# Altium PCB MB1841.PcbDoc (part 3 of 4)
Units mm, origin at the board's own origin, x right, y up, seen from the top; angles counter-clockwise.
Board outline 70 x 82.5 mm, 4 copper layers (Top Layer, Signal Layer 1, Signal Layer 2, Bottom Layer), stack 1.49 mm thick; 252 components, 169 nets, 1058 pads, 796 vias.
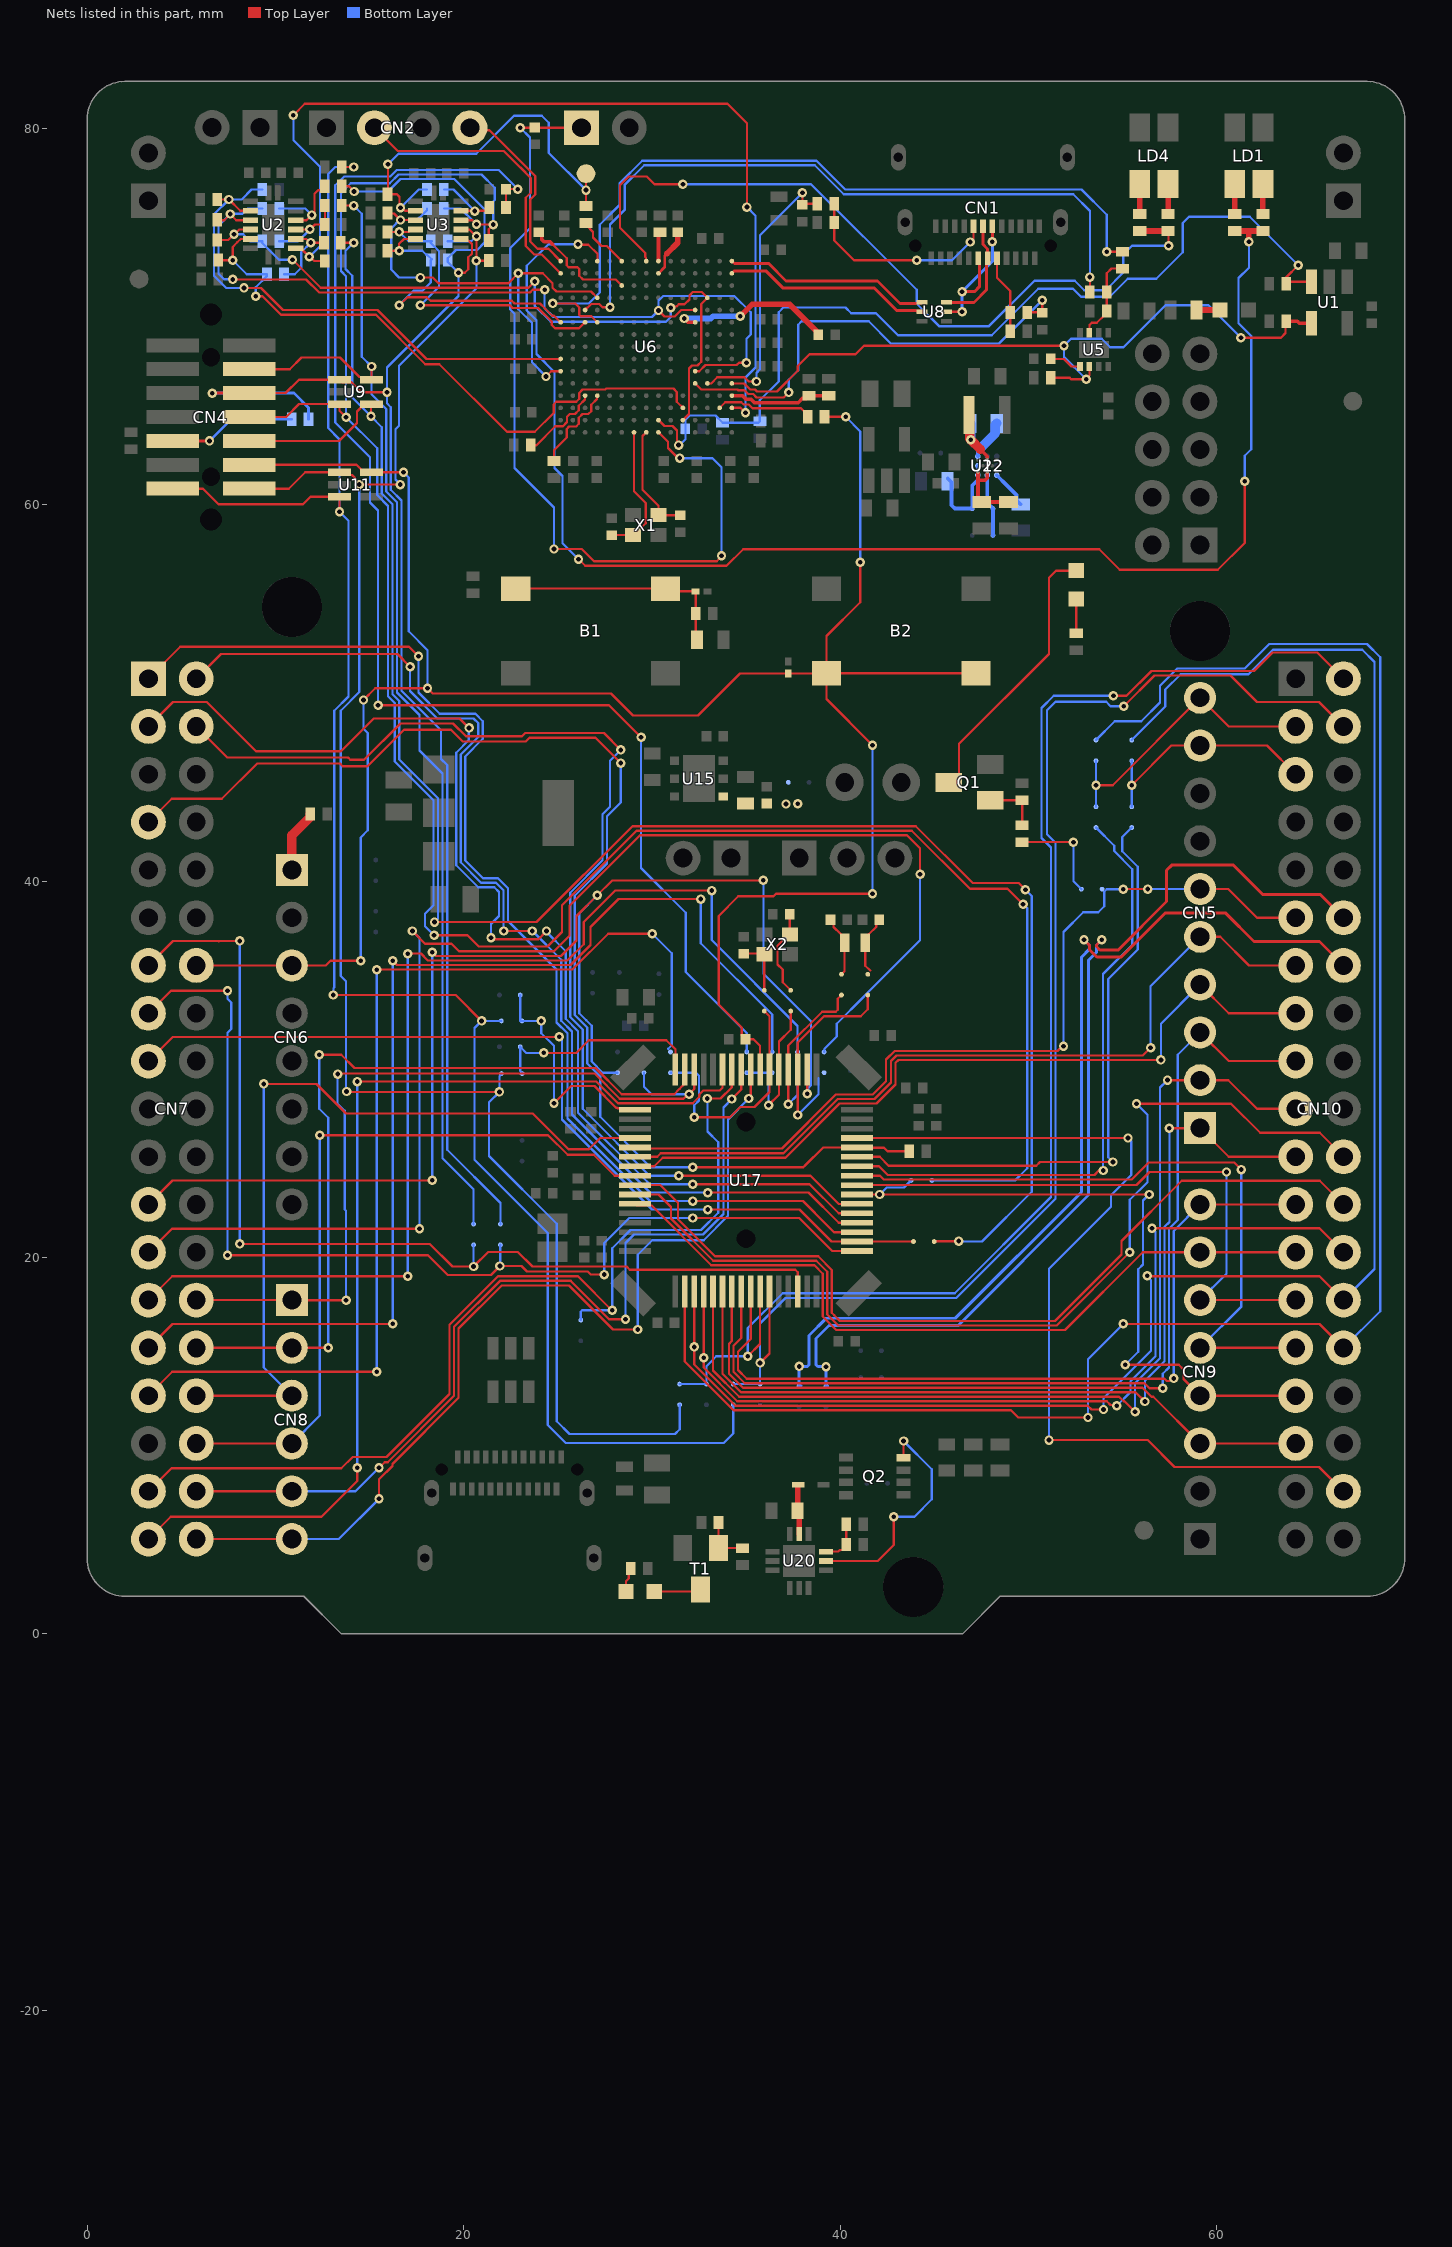
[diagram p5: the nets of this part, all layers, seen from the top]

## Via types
v1: diameter 0.5, hole 0.25, Top Layer to Bottom Layer, tented both sides, 796 vias

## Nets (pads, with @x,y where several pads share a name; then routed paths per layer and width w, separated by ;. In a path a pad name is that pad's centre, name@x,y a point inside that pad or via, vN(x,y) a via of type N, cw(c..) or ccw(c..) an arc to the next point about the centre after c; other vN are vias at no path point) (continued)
JTDI_BP: R21.1 R109.2 U2.11 | length 4.2
  Top Layer w0.12: U2.11@11.075,74.125 11.632,74.125 11.822,73.935 v1(11.88,73.935) ; v1@11.885,73.935 v1(11.88,73.935) ; v1@11.9,73.9 11.925,73.925 R21.1@12.575,73.925 ; v1@11.9,73.925 11.89,73.925 v1(11.88,73.935)
  Bottom Layer w0.12: R109.2@10.45,72.25 11.025,72.25 11.37,72.595 11.37,73.425 11.86,73.915 v1@11.865,73.915
MCO_BP: R7.1 R102.2 U3.14 | length 3.7
  Top Layer w0.12: U3.14@19.85,75.625 v1@20.61,75.625 ; v1(20.593,75.608) v1@20.61,75.625 ; R7.1@21.35,75.8 21.175,75.625 v1@20.61,75.625
  Bottom Layer w0.12: R102.2@18.95,76.75 19.452,76.75 20.487,75.715 v1@20.595,75.715
MCU.JTDI: CN4.10 R21.2 SB41.1 U9.4 | length 104.7
  Top Layer w0.12: CN4.10@8.602,63.395 13.37,63.395 14.325,64.35 14.325,64.955 14.72,65.35 U9.4@15.1,65.35 15.075,65.325 v1(15.075,64.7) ; R21.2@13.575,73.95 13.6,73.925 v1(14.15,73.925) ; v1(18.45,37.825) 23.875,37.825 28.975,42.925 44.025,42.925 47.05,39.9 49.5,39.9 v1(49.85,39.55) ; SB41.1@45,20.85 45.01,20.86 46.285,20.86 v1(46.3,20.875)
  Bottom Layer w0.12: v1(14.15,73.925) 13.72,73.495 13.72,72.53 14.075,72.175 14.075,65.7 v1(15.075,64.7) 15.65,64.125 15.65,60.604 16.22,60.034 16.22,49.926 16.575,49.571 16.575,46.464 18.64,44.399 18.64,38.008 18.45,37.818 v1(18.45,37.825) ; v1(46.3,20.875) 46.325,20.85 47.545,20.85 50.185,23.49 50.185,39.215 v1(49.85,39.55)
MCU.MCO: C6.1 R7.2 SB20.1 | length 74.4
  Top Layer w0.12: v1(15.45,49.35) 27.725,49.35 v1(29.425,47.65) ; R7.2@22.25,75.8 C6.1@22.25,76.775 v1(22.875,76.775)
  Bottom Layer w0.12: v1(15.45,49.35) 15.45,59.7 15.025,60.125 15.025,62.525 13.175,64.375 13.175,76.975 13.65,77.45 16.1,77.45 16.44,77.79 21.86,77.79 v1(22.875,76.775) ; v1(29.425,47.65) 29.425,40.7 31.8,38.325 31.8,35.175 32.5,34.475 35.04,31.935 SB20.1@35.04,30.925
MCU.SWCLK: CN4.6 R2.2 R66.1 R105.2 SB29.1 U3.11 U9.1 | length 87
  Top Layer w0.12: CN4.6@8.602,65.935 10.535,65.935 11.25,66.65 U9.1@13.4,66.65 13.54,66.51 14.04,66.51 14.576,65.974 15.924,65.974 v1(15.925,65.975) ; R2.2@13.525,76.925 13.9,76.925 v1(14.175,76.65) ; v1(19.725,72.325) 20.06,72.325 20.245,72.51 20.245,73.153 20.435,73.343 20.435,73.855 20.255,74.035 19.94,74.035 U3.11@19.85,74.125
  Top Layer w0.15: v1@6.641,65.93 v1(6.646,65.935) CN4.6@8.602,65.935
  Bottom Layer w0.12: v1(14.175,76.65) 15.979,76.65 16.639,77.31 19.5,77.31 21.112,75.698 21.112,74.617 ; 21.11,74.615 21.112,74.617 ; SB29.1@21.95,21.775 21.95,22.9 19.12,25.73 19.12,46.172 18.8,46.492 18.8,48.025 16.7,50.125 16.7,60.233 16.13,60.803 16.13,65.184 15.925,65.389 v1(15.925,65.975) 15.925,67.3 19.725,71.1 v1(19.725,72.325) 19.725,72.33 19.15,72.905 R105.2@19.15,73 19.15,73.095 19.595,73.54 20.72,73.54 21.112,73.932 21.112,74.617
  Bottom Layer w0.15: v1(6.646,65.935) 10.976,65.935 11.753,65.158 R66.1@11.753,64.541
MCU.SWDIO: CN4.4 R6.2 SB30.1 U9.5 | length 65.2
  Top Layer w0.12: CN4.4@8.7,67.205 10.755,67.205 11.375,67.825 13.425,67.825 14.46,66.79 14.96,66.79 U9.5@15.1,66.65 15.105,66.655 v1(15.105,67.35) ; R6.2@13.525,75.9 v1(14.15,75.9)
  Bottom Layer w0.12: v1(14.15,75.9) 14.589,75.461 14.589,67.866 v1(15.105,67.35) 15.105,65.87 15.89,65.085 15.89,60.703 16.46,60.133 16.46,50.026 17.65,48.836 17.65,47.45 17.65,46.95 18.88,45.72 18.88,25.27 20.525,23.625 SB30.1@20.525,21.775
MCU.SWO: CN4.8 R20.1 R103.2 SB28.2 U3.13 U9.3 | length 119.5
  Top Layer w0.12: CN4.8@8.602,64.665 10.565,64.665 11.25,65.35 U9.3@13.4,65.35 13.4,65 v1(13.75,64.65) ; v1(18.425,37.125) 20.2,37.125 20.8,36.525 24.45,36.525 25.225,37.3 25.225,38.725 29.185,42.685 43.815,42.685 46.9,39.6 48.9,39.6 v1(49.725,38.775) ; U3.13@19.85,75.125 20.457,75.125 v1(20.682,74.9) ; v1@20.7,74.9 20.705,74.895 21.565,74.895 v1(21.57,74.89) ; R20.1@21.32,74.055 R20.1@21.325,74.05 21.325,74.645 v1(21.57,74.89) ; v1@21.585,74.89 v1(21.57,74.89)
  Bottom Layer w0.12: v1(18.425,37.125) 17.95,37.6 17.95,38.275 18.4,38.725 18.4,44.3 16.335,46.365 16.335,49.472 15.98,49.827 15.98,59.934 15.4,60.514 15.4,63 v1(13.75,64.65) 13.75,72.15 13.48,72.42 13.48,76.563 13.997,77.08 16.069,77.08 16.539,77.55 20.945,77.55 21.65,76.845 21.65,76.19 21.57,76.11 21.57,74.925 v1@21.56,74.915 ; R103.2@18.95,75.75 19.832,75.75 20.595,74.987 v1@20.595,74.905 ; v1(21.57,74.89) v1@21.577,74.897 ; SB28.2@44.875,24.1 49.3,24.1 49.945,24.745 49.945,38.555 v1(49.725,38.775)
MCU.VCP_RX: CN4.13 R1.2 SB16.1 SB35.1 U11.3 | length 101.1
  Top Layer w0.12: CN4.13@4.55,60.85 6.15,60.85 6.975,60.025 11.461,60.025 11.861,60.425 U11.3@13.4,60.425 v1(13.4,59.625) ; v1(13.075,33.95) 19.575,33.95 v1(20.95,32.575) ; R1.2@13.525,77.95 v1(14.15,77.95)
  Bottom Layer w0.12: v1(13.075,33.95) 13.084,33.959 13.084,34.309 13.125,34.35 13.125,49.062 13.875,49.812 13.875,59.15 v1(13.4,59.625) ; v1@13.375,59.725 13.4,59.75 13.4,63.475 12.8,64.075 12.8,77.575 13.175,77.95 v1(14.15,77.95) ; v1(20.95,32.575) 20.575,32.2 20.575,25.2 24.47,21.305 24.47,11.101 25.426,10.145 33.82,10.145 34.325,10.65 SB35.1@34.325,12.175 ; 21.208,32.575 SB16.1@22,32.575
MCU.VCP_TX: CN4.14 R25.1 R104.2 SB26.1 SB37.1 U3.12 U11.1 | length 96.2
  Top Layer w0.12: CN4.14@8.602,60.855 10.705,60.855 11.575,61.725 U11.1@13.4,61.725 13.6,61.725 13.74,61.585 14.065,61.585 14.221,61.429 14.221,61.304 v1(14.45,61.075) v1(16.625,61.075) ; v1@14.003,28.8 v1(21.9,28.8) ; U3.12@19.85,74.625 19.86,74.615 20.305,74.615 20.61,74.31 v1@20.67,74.31 ; v1@20.665,74.32 20.678,74.307 20.678,72.978 v1(20.675,72.975) R25.1@21.325,72.975
  Bottom Layer w0.12: v1(13.775,28.825) 13.75,28.85 13.75,34.675 13.465,34.96 13.465,49.062 14.45,50.047 v1(14.45,61.075) ; v1(16.625,61.075) 16.625,61.088 16.37,61.343 16.37,64.009 16.561,64.2 16.561,67.386 20.675,71.5 v1(20.675,72.975) ; R104.2@19.15,74 20.407,74 v1(20.682,74.275) v1@20.68,74.28 ; SB26.1@22,29.775 22,29.739 21.9,29.639 v1(21.9,28.8) 21.35,28.25 21.35,25.4 24.95,21.8 24.95,11.3 25.625,10.625 31.225,10.625 31.475,10.875 SB37.1@31.475,12.175
NetB1_3: B1.3 B1.4 R48.2 R50.1 U13.1 | length 12.2
  Top Layer w0.12: B1.3@22.77,55.55 B1.4@30.72,55.55 30.87,55.4 U13.1@32.325,55.4 R48.2@32.325,54.225 32.325,52.9 R50.1@32.4,52.825
NetC8_2: C8.2 U6.F13 | length 6.1
  Top Layer w0.12: 24.725,73.85 25.475,73.1 25.475,72.725 25.575,72.625 26.05,72.625 26.145,72.53 26.145,72.174 26.344,71.975 28.075,71.975 U6.F13@28.4,71.65
  Top Layer w0.2: C8.2@24,74.475 24.15,74.325 24.15,74.1 24.275,73.975 24.6,73.975 24.725,73.85
NetC12_2: C12.2 U6.J14 | length 2.6
  Top Layer w0.15: U6.J14@30.35,72.3 30.68,72.63 30.68,73.23 30.8,73.35
  Top Layer w0.3: 30.8,73.35 31.375,73.925 C12.2@31.375,74.475 C12.2@31.375,74.494
NetC21_2: C21.2 U6.M10 | length 8.6
  Top Layer w0.2: v1(31.725,69.9) 31.925,69.7 U6.M10@32.295,69.7
  Top Layer w0.3: v1(34.7,70.025) 35.325,70.65 37.325,70.65 C21.2@38.75,69.225
  Bottom Layer w0.3: v1(31.725,69.9) 33.131,69.9 33.256,70.025 v1(34.7,70.025)
NetC24_2: C24.2 U5.1 | length 1.8
  Top Layer w0.12: C24.2@51.2,67.75 51.9,67.75 52.3,67.35 U5.1@52.75,67.35 U5.1@52.75,67.25
NetC44_2: C44.2 C46.2 SB8.1 U15.4
  other v1: 37.125,44.1 37.755,44.11
NetC71_2: C71.2 D1.2 U20.8 | length 2.7
  Top Layer w0.3: D1.2@37.775,7.925 37.75,7.925 C71.2@37.75,6.55 37.825,6.475 U20.8@37.825,5.3
NetCN1_A5: CN1.A5 R34.1 R36.1 | length 4.2
  Top Layer w0.12: CN1.A5@48.342,73.103 48.342,72.058 49.05,71.35 R34.1@49.05,70.225 R36.1@49.05,69.225
NetCN1_B5: CN1.B5 R5.1 R16.1 | length 10.9
  Top Layer w0.12: R16.1@39.65,75 39.697,75.047 R5.1@39.697,76 ; R16.1@39.697,75 39.697,74.045 40.742,73 v1(44.069,73) ; v1(46.915,73.965) 47.092,74.141 CN1.B5@47.092,74.803
  Bottom Layer w0.12: v1(44.069,73) 45.95,73 v1(46.915,73.965)
NetCN4_9: CN4.9 R66.2 | length 6.8
  Top Layer w0.15: CN4.9@4.538,63.395 v1(6.494,63.395) v1@6.499,63.4
  Bottom Layer w0.15: v1(6.494,63.395) 7.64,64.541 R66.2@10.853,64.541
NetCN6_1: CN6.1 R52.2 | length 3.4
  Top Layer w0.5: CN6.1@10.87,40.6 10.87,42.438 11.845,43.413 11.845,43.57 R52.2@11.85,43.575
NetL1_1: L1.1 R62.1 U12.C3 | length 3.6
  Top Layer w0.2: 47.45,62.95 47.825,62.575 U12.C3@47.825,62.387
  Top Layer w0.5: L1.1@46.85,64.775 46.9,64.725 v1@46.9,63.5 ; v1(46.95,63.45) 47.45,62.95
  Bottom Layer w0.5: R62.1@46.925,64.325 46.95,64.3 v1(46.95,63.45)
NetLD1_1: LD1.1 R13.1 | length 1.7
  Top Layer w0.3: R13.1@62.47,75.345 R13.1@62.47,75.45 LD1.1@62.47,77.05
NetLD1_2: LD1.2 R12.2 | length 1.5
  Top Layer w0.3: R12.2@60.97,75.515 LD1.2@60.97,77.04
NetLD2_1: LD2.1 R49.1 | length 1.8
  Top Layer w0.12: LD2.1@52.55,55 52.55,53.225 R49.1@52.575,53.2
NetLD2_2: LD2.2 Q1.3 | length 14.8
  Top Layer w0.12: Q1.3@45.775,45.25 45.885,45.25 46.325,45.69 46.325,47.3 51.1,52.075 51.1,56.125 51.475,56.5 LD2.2@52.55,56.5
NetLD3_1: LD3.1 R32.1 | length 1.2
  Top Layer w0.3: R32.1@58.95,70.35 LD3.1@60.2,70.35
NetLD4_1: LD4.1 R11.1 | length 1.6
  Top Layer w0.3: R11.1@57.431,75.444 LD4.1@57.431,77.044
NetLD4_2: LD4.2 R10.1 | length 1.6
  Top Layer w0.3: R10.1@55.925,75.45 LD4.2@55.925,77.05
NetLD6_1: LD6.1 R61.1 | length 1.2
  Top Layer w0.12: LD6.1@28.625,2.25 28.625,2.8 28.775,2.95 R61.1@28.775,3.375
NetLD6_2: LD6.2 T1.3 | length 2.5
  Top Layer w0.12: LD6.2@30.125,2.25 32.475,2.25 T1.3@32.588,2.362
NetQ1_1: Q1.1 R51.2 R53.2 | length 2.8
  Top Layer w0.12: Q1.1@47.975,44.3 R51.2@49.675,44.3 R53.2@49.675,43.225
NetQ2_4: Q2.4 U20.5 | length 12.5
  Top Layer w0.12: U20.5@39.25,3.875 42,3.875 42.85,4.725 v1(42.85,6.225) ; Q2.4@43.375,9.35 v1(43.375,10.25)
  Bottom Layer w0.12: v1(42.85,6.225) 43.95,6.225 44.875,7.15 44.875,8.75 v1(43.375,10.25)
NetR8_1: R8.1 U6.F15 | length 3
  Top Layer w0.12: R8.1@26.5,74.975 26.526,74.949 26.526,74.85 26.874,74.501 26.874,74.201 27.325,73.75 27.6,73.75 U6.F15@28.4,72.95
NetR14_1: R14.1 U6.J15 | length 1.5
  Top Layer w0.2: U6.J15@30.35,72.95 R14.1@30.35,74.475
NetR23_1: R23.1 R30.1 R33.1 U5.7 | length 4.3
  Top Layer w0.12: U5.7@53.25,69.15 53.25,69.55 53.375,69.675 53.645,69.675 54.045,70.075 R33.1@54.1,70.075 ; R30.1@54.175,71.3 54.175,70.375 R33.1@54.2,70.35 ; R30.1@54.2,71.325 54.175,71.35 54.175,72.3 54.425,72.55 R23.1@55,72.55
NetR40_1: R40.1 U6.P3 | length 5.2
  Top Layer w0.12: U6.P3@33.6,65.15 33.905,65.455 34.745,65.455 34.875,65.325 35.153,65.325 35.353,65.125 37.92,65.125 38.275,64.77 R40.1@38.275,64.675
NetR44_1: R44.1 U6.D4 | length 4.8
  Top Layer w0.12: R44.1@24.8,62.325 24.8,62.9 25.475,63.575 25.475,64.033 25.602,64.16 25.976,64.16 26.117,64.302 26.117,64.629 26.313,64.825 26.625,64.825 26.775,64.975 26.775,65.312 27.079,65.616 27.079,65.779 U6.D4@27.1,65.8
NetR45_1: R45.1 R46.1 U12.A1 U12.C1 | length 4
  Top Layer w0.2: 47.325,61.3 47.7,61.3 47.825,61.425 U12.C1@47.825,61.763 ; U12.A1@47.325,61.763 47.325,60.35 R45.1@47.525,60.15 R46.1@48.95,60.15
NetR53_1: R53.1 SB10.2 | length 5.4
  Top Layer w0.12: R53.1@49.675,42.075 v1(52.4,42.075)
  Bottom Layer w0.12: v1(52.4,42.075) 52.4,40 SB10.2@52.825,39.575
NetR57_2: R57.2 R60.2 T1.1 | length 2.6
  Top Layer w0.12: R57.2@33.538,5.912 T1.1@33.538,4.563 R60.2@34.813,4.563
NetR58_2: R58.2 R59.1 U20.6 | length 2.4
  Top Layer w0.12: U20.6@39.25,4.375 39.9,4.375 39.99,4.465 40.13,4.465 40.325,4.66 R59.1@40.325,4.75 R58.2@40.325,5.825
NetR62_2: R62.2 U22.A1 | length 2.2
  Bottom Layer w0.2: U22.A1@47.325,62.575 47.333,62.583 47.333,62.803 47.475,62.944 47.475,63.05
  Bottom Layer w0.5: 47.5,63.05 48.255,63.805 48.255,64.255 R62.2@48.325,64.325
NetR63_2: R63.2 SB6.1 U22.A2 U22.A3 | length 5.1
  Bottom Layer w0.2: R63.2@45.725,61.4 45.925,61.2 45.925,59.975 46.1,59.8 SB6.1@47.025,59.8 47.025,61.025 47.325,61.325 U22.A3@47.325,61.575 U22.A2@47.325,62.075
NetR64_1: R64.1 U22.C3 | length 2.1
  Bottom Layer w0.2: U22.C3@48.325,61.575 48.875,61.025 49.372,60.528 49.372,60.245 49.592,60.025 R64.1@49.6,60.025
NetR65_1: R65.1 U6.C4 | length 4.4
  Top Layer w0.12: R65.1@23.568,63.17 23.864,63.17 24.871,64.177 25.275,64.177 25.491,64.393 25.491,64.683 25.629,64.821 25.912,64.821 26.116,65.025 26.116,65.263 26.45,65.597 U6.C4@26.45,65.8
NetSB1_2: SB1.2 SB18.2 U17.4 | length 9.3
  Top Layer w0.12: v1(37.25,28.15) U17.4@37.25,30 37.25,31.264 39.051,33.065 39.775,33.065 39.875,33.165 39.875,33.75 SB1.2@40.075,33.95
  Bottom Layer w0.12: v1(37.25,28.15) 37.74,28.64 SB18.2@37.74,29.825
NetSB2_2: SB2.2 SB22.2 U17.3 | length 11.6
  Top Layer w0.12: v1@37.75,27.475 v1(37.75,27.575) U17.3@37.75,30 37.75,31.425 39.15,32.825 41.1,32.825 41.475,33.2 SB2.2@41.475,33.95
  Bottom Layer w0.12: v1(37.75,27.575) 38.85,28.675 38.85,29.525
NetSB3_2: SB3.2 SB21.2 U17.6 | length 12.9
  Top Layer w0.12: v1(32.25,27.45) 34.15,27.45 34.7,28 35.45,28 36.25,28.8 U17.6@36.25,30 36.25,32.825 SB3.2@35.975,33.1
  Bottom Layer w0.12: SB21.2@30.99,29.825 32.34,29.825 32.5,29.665 32.5,28.339 32.25,28.089 v1(32.25,27.45)
NetSB4_2: SB4.2 SB19.2 SB20.2 U17.5 | length 8.6
  Top Layer w0.12: v1(36.2,28.1) 36.75,28.65 U17.5@36.75,30 36.75,31.475 37.375,32.1 SB4.2@37.375,33.1
  Bottom Layer w0.12: SB20.2@35.04,29.825 SB19.2@36.39,29.825 36.2,29.635 v1(36.2,28.1)
NetSB6_2: SB6.2 SB7.2 U22.B3 | length 3.3
  Bottom Layer w0.2: U22.B3@47.825,61.575 47.825,60.1 SB6.2@48.125,59.8 SB7.2@48.125,58.375
NRST: B2.1 B2.2 C55.2 CN4.12 CN6.3 CN7.14 R40.2 U11.5 U14.1 U17.7 | length 124.1
  Top Layer w0.12: CN7.14@5.79,35.52 CN6.3@10.87,35.52 12.67,35.52 12.925,35.775 v1(14.525,35.775) ; CN4.12@8.7,62.125 14.3,62.125 14.7,61.725 U11.5@15.1,61.725 v1(16.8,61.725) ; v1(14.675,49.625) 15.3,50.25 v1(18.075,50.25) 18.35,49.975 27.825,49.975 29,48.8 32.45,48.8 34.688,51.038 U14.1@37.25,51.038 39.268,51.038 B2.1@39.275,51.045 ; U17.7@35.75,30 35.75,31.25 35.4,31.6 C55.2@34.975,31.6 34.78,31.795 34.78,32.22 33.55,33.45 33.55,38.15 34.595,39.195 36.462,39.195 36.592,39.325 v1(41.725,39.325) ; R40.2@39.175,64.675 v1(40.3,64.675) ; v1(41.075,56.95) 41.075,54.825 39.28,53.03 B2.1@39.28,51.05 ; v1(41.725,47.225) 39.275,49.675 B2.1@39.275,51.045 ; B2.2@47.23,51.05 B2.1@39.28,51.05 ; B2.1@39.275,51.045 B2.1@39.28,51.05
  Bottom Layer w0.12: v1(14.525,35.775) 14.525,42.325 14.9,42.7 14.9,47.875 14.675,48.1 v1(14.675,49.625) ; v1(16.8,61.725) 17.075,61.45 17.075,53.275 18.075,52.275 v1(18.075,50.25) ; v1(40.3,64.675) 41.075,63.9 v1(41.075,56.95) ; v1(41.725,39.325) v1(41.725,47.225)
OSC32_IN: C50.2 SB2.1 X3.2 | length 3.1
  Top Layer w0.12: 41.6,35.25 41.34,35.51 X3.2@41.34,36.725 41.53,36.915 41.53,37.18 41.92,37.57 41.92,37.78 C50.2@42.09,37.95
OSC32_OUT: C49.2 SB1.1 X3.1 | length 3.3
  Top Layer w0.12: C49.2@39.49,37.95 39.657,37.783 39.657,37.568 40.05,37.175 40.05,36.915 X3.1@40.24,36.725 40.24,35.215 SB1.1@40.075,35.05
OSC_IN: C48.2 SB4.1 X2.1 | length 4.6
  Top Layer w0.12: C48.2@37.327,38.244 37.327,37.169 37.012,36.854 36.954,36.854 36.675,36.575 36.675,35.575 36.95,35.3 36.95,34.625 SB4.1@37.375,34.2
OSC_OUT: C51.2 SB3.1 X2.3 | length 3
  Top Layer w0.12: C51.2@34.875,36.15 35.95,36.15 X2.3@35.981,36.119 ; SB3.1@35.975,34.2 35.975,36.116 X2.3@35.977,36.119
PA0: CN7.28 CN8.1 SB23.2 U17.14 | length 44.3
  Top Layer w0.12: CN7.28@5.79,17.74 CN8.1@10.87,17.74 10.885,17.725 v1(13.75,17.725) ; v1(13.3,29.75) 13.33,29.78 26.958,29.78 28.296,28.443 31.682,28.443 31.915,28.675 v1(31.975,28.675) 32.25,28.95 U17.14@32.25,30
  Bottom Layer w0.12: v1(13.3,29.75) 13.3,28.175 13.675,27.8 13.675,22.555 13.75,22.48 v1(13.75,17.725) ; SB23.2@29.575,29.825 29.575,29.075 29.975,28.675 v1(31.975,28.675)
PA1: CN7.30 CN8.2 U17.15 | length 44.1
  Top Layer w0.12: CN7.30@5.79,15.2 CN8.2@10.87,15.2 v1(12.8,15.2) ; v1(12.325,30.775) 13.5,30.775 14.2,30.075 27.003,30.075 28.395,28.683 31.183,28.683 31.47,28.97 31.475,28.97 31.58,29.075 31.58,29.08 31.66,29.16 31.66,29.91 U17.15@31.75,30
  Bottom Layer w0.12: v1(12.325,30.775) 12.325,27.9 12.8,27.425 v1(12.8,15.2)
PA2: SB17.1 SB26.2 U17.16 | length 11.4
  Top Layer w0.12: v1(24.25,30.875) 25.975,30.875 26.65,31.55 30.765,31.55 31.25,31.065 U17.16@31.25,30
  Bottom Layer w0.12: SB26.2@23.1,29.775 23.1,29.811 23,29.911 SB17.1@23,31.2 23.325,30.875 v1(24.25,30.875)
PA3: SB15.1 SB16.2 U17.17 | length 12.3
  Top Layer w0.12: v1(24.8,28.2) 25.71,29.11 26.949,29.11 28.097,27.963 28.137,27.963 28.168,27.932 29.018,27.932 U17.17@29.1,27.85
  Bottom Layer w0.12: SB15.1@23.01,33.94 23.01,32.565 SB16.2@23.02,32.575 ; SB16.2@23.1,32.575 v1(24.125,32.575) 24.125,31.925 24.8,31.25 v1(24.8,28.2)
PA4: CN7.32 CN8.3 U17.20 | length 43.7
  Top Layer w0.12: CN7.32@5.79,12.66 CN8.3@10.87,12.66 ; v1(9.375,29.225) 12.175,29.225 13.75,27.65 23.675,27.65 25.575,25.75 26.65,25.75 27.25,26.35 U17.20@29.1,26.35
  Bottom Layer w0.12: v1(9.375,29.225) 9.375,14.155 CN8.3@10.87,12.66
PA5: CN5.6 CN10.11 SB10.1 U17.21 | length 46.2
  Top Layer w0.12: U17.21@29.1,25.85 29.15,25.8 36.917,25.8 39.777,28.66 41.731,28.66 42.44,29.369 42.44,30.519 42.901,30.98 51.555,30.98 51.8,31.225 v1(51.875,31.225) ; v1(55.05,39.575) 55.054,39.579 v1(56.354,39.579) ; CN5.6@59.13,39.584 60.627,39.584 62.151,38.06 CN10.11@64.21,38.06
  Bottom Layer w0.12: v1(51.875,31.225) 51.875,37.3 52.925,38.35 53.725,38.35 54.036,38.661 54.036,39.438 54.173,39.575 v1(55.05,39.575) ; v1@56.359,39.584 CN5.6@59.13,39.584
PA6: CN5.5 CN10.13 U17.22 | length 43.2
  Top Layer w0.12: U17.22@29.1,25.35 30.286,25.35 30.476,25.54 36.996,25.54 39.876,28.42 41.831,28.42 42.71,29.299 42.71,30.449 43.001,30.74 56.09,30.74 v1(56.5,31.15) ; CN5.5@59.13,37.044 60.206,37.044 61.73,35.52 CN10.13@64.21,35.52
  Bottom Layer w0.12: v1(56.5,31.15) 56.5,34.414 CN5.5@59.13,37.044
PA7: CN5.4 CN10.15 U17.23 | length 41.5
  Top Layer w0.12: U17.23@29.1,24.85 30.125,24.85 30.575,25.3 37.095,25.3 39.975,28.18 41.93,28.18 42.95,29.2 42.95,30.35 43.1,30.5 v1(57.05,30.5) ; CN5.4@59.13,34.504 60.654,32.98 CN10.15@64.21,32.98
  Bottom Layer w0.12: v1(57.05,30.5) 57.05,32.424 CN5.4@59.13,34.504
PA8: CN9.8 CN10.23 U17.41 | length 42.8
  Top Layer w0.12: U17.41@35.25,18.2 35.25,15.675 34.575,15 34.575,14.025 35.035,13.565 57.243,13.565 57.365,13.443 57.49,13.443 57.622,13.575 v1(57.725,13.575) ; CN9.8@59.13,22.82 CN10.23@64.21,22.82
  Bottom Layer w0.12: v1(57.725,13.575) 57.725,21.415 CN9.8@59.13,22.82
PA9: CN10.2 SB36.2 SB37.2 U17.42 | length 73
  Top Layer w0.12: v1(35.1,14.75) 35.75,15.4 U17.42@35.75,18.2 ; v1(54.525,49.85) 55.225,49.85 56.544,51.169 61.994,51.169 62.975,52.15 65.36,52.15 CN10.2@66.75,50.76
  Bottom Layer w0.12: SB37.2@31.475,13.275 SB36.2@32.9,13.275 32.9,14.217 33.18,14.497 33.18,14.506 33.424,14.75 v1(35.1,14.75) 35.1,16.25 36.957,18.107 46.093,18.107 51.205,23.219 51.205,41.79 50.705,42.29 50.705,49.206 51.349,49.85 v1(54.525,49.85)
PA10: CN10.4 SB34.2 SB35.2 U17.43 | length 71.1
  Top Layer w0.12: v1(35.75,14.4) 36.25,14.9 U17.43@36.25,18.2 ; v1(55.075,49.3) 56.704,50.929 60.746,50.929 62.15,49.525 65.445,49.525 CN10.4@66.75,48.22
  Bottom Layer w0.12: SB35.2@34.325,13.275 SB34.2@35.75,13.275 v1(35.75,14.4) 35.75,16.5 37.1,17.85 46.175,17.85 51.445,23.12 51.445,31.403 51.447,31.405 51.447,42.047 51,42.494 51,49.081 51.449,49.53 54.14,49.53 54.37,49.3 v1(55.075,49.3)
PA11: CN10.14 SB38.1 | length 51
  Top Layer w0.155: v1(52.961,36.886) 53.246,36.602 53.246,36.365 53.645,35.966 54.939,35.966 57.273,38.3 60.5,38.3 62,36.8 65.47,36.8 CN10.14@66.75,35.52
  Bottom Layer w0.155: SB38.1@37.919,13.189 37.913,13.183 37.843,13.183 SB38.1@37.824,13.164 v1(37.824,14.214) 37.831,14.207 38.256,14.207 38.346,14.298 38.346,15.86 39.261,16.775 46.125,16.775 52.825,23.475 52.825,35.958 53.246,36.379 53.246,36.602 v1(52.961,36.886)
PA12: CN10.12 SB39.1 | length 52.3
  Top Layer w0.155: v1(53.911,36.886) 53.627,36.602 53.627,36.523 53.803,36.347 54.782,36.347 57.35,38.916 57.35,40.575 57.625,40.85 60.9,40.85 62.45,39.3 65.51,39.3 CN10.12@66.75,38.06
  Bottom Layer w0.155: SB39.1@39.345,13.175 39.339,13.169 39.269,13.169 SB39.1@39.25,13.15 v1(39.25,14.2) 39.243,14.207 38.818,14.207 38.727,14.298 38.727,15.702 39.419,16.394 46.283,16.394 53.206,23.317 53.206,35.8 53.627,36.221 53.627,36.602 v1(53.911,36.886)
PA13: CN7.13 SB30.2 U17.46 | length 54.6
  Top Layer w0.12: CN7.13@3.25,35.52 4.555,36.825 7,36.825 ; 6.975,36.8 7,36.825 ; v1(8.1,20.725) 18.2,20.725 19.4,19.525 v1(20.525,19.525) 21.3,20.3 22.875,20.3 23.65,19.525 28.65,19.525 28.825,19.35 37.625,19.35 37.75,19.225 U17.46@37.75,18.2 ; v1(8.1,36.825) 7,36.825
  Bottom Layer w0.12: v1(8.1,20.725) v1(8.1,36.825) ; v1(20.525,19.525) SB30.2@20.525,20.675
PA14: CN7.15 SB29.2 U17.49 | length 57.3
  Top Layer w0.12: CN7.15@3.25,32.98 4.445,34.175 v1(7.45,34.175) ; v1(7.45,20.125) 18.1,20.125 19.15,19.075 21.45,19.075 v1(21.925,19.55) 23.075,19.55 23.363,19.263 26.587,19.263 26.755,19.095 v1(27.47,19.095) ; v1(32.175,22.1) 37.829,22.1 39.579,20.35 U17.49@40.9,20.35
  Bottom Layer w0.12: v1(7.45,20.125) 7.45,31.95 7.65,32.15 7.65,33.55 7.45,33.75 v1(7.45,34.175) ; v1(21.925,19.55) 21.937,19.562 21.937,20.663 SB29.2@21.95,20.675 ; v1(27.47,19.095) 27.47,20.77 28.8,22.1 v1(32.175,22.1)
PA15: CN7.17 SB41.2 U17.50 | length 48.2
  Top Layer w0.12: CN7.17@3.25,30.44 4.535,31.725 v1(25.075,31.725) ; v1(32.975,22.55) 37.85,22.55 39.55,20.85 U17.50@40.9,20.85 SB41.2@43.9,20.85
  Bottom Layer w0.12: v1(25.075,31.725) 25.23,31.57 25.23,27.331 30.011,22.55 v1(32.975,22.55)
PB0: CN7.34 CN8.4 U17.24 | length 39.7
  Top Layer w0.12: CN7.34@5.79,10.12 CN8.4@10.87,10.12 ; v1(12.35,26.5) 24.486,26.5 25.526,25.46 26.915,25.46 28.025,24.35 U17.24@29.1,24.35
  Bottom Layer w0.12: CN8.4@10.87,10.12 12.35,11.6 v1(12.35,26.5)
PB1: CN10.24 U17.25 | length 46.5
  Top Layer w0.12: U17.25@29.1,23.85 30.45,23.85 31.393,22.907 31.393,22.036 33.359,20.07 38.834,20.07 39.56,19.344 39.56,17.069 39.689,16.939 39.999,16.63 51.416,16.63 54.95,20.164 54.95,20.875 58.15,24.075 65.495,24.075 CN10.24@66.75,22.82
PB2: CN10.22 U17.26 | length 53.2
  Top Layer w0.12: U17.26@29.1,23.35 30.35,23.35 31.018,22.682 31.018,22.072 33.259,19.83 38.734,19.83 39.32,19.244 39.32,16.969 39.899,16.39 51.515,16.39 v1(55.4,20.275) ; v1(55.75,28.175) 60.775,28.175 62.325,26.625 65.485,26.625 CN10.22@66.75,25.36
  Bottom Layer w0.12: v1(55.4,20.275) 55.4,23.066 56.337,24.003 56.337,27.588 v1(55.75,28.175)
PB3: CN9.4 CN10.31 SB28.1 U17.55 | length 37.1
  Top Layer w0.12: U17.55@40.9,23.35 v1(42.1,23.35) v1(56.425,23.35) ; v1(55.15,14.3) 58,14.3 58.25,14.05 58.25,13.54 CN9.4@59.13,12.66 CN10.31@64.21,12.66
  Bottom Layer w0.12: v1(42.1,23.35) 42.475,23.725 43.4,23.725 SB28.1@43.775,24.1 ; v1(55.15,14.3) 55.85,15 55.85,19.376 56.1,19.626 56.1,23.025 v1(56.425,23.35)
PB4: CN9.6 CN10.27 U17.56 | length 32.4
  Top Layer w0.12: U17.56@40.9,23.85 55.75,23.85 56.445,24.545 v1(60.535,24.545) ; CN9.6@59.13,17.74 CN10.27@64.21,17.74
  Bottom Layer w0.12: CN9.6@59.13,17.74 60.535,19.145 v1(60.535,24.545)
PB5: CN9.5 CN10.29 U17.57 | length 36.5
  Top Layer w0.12: U17.57@40.9,24.35 42.125,24.35 42.325,24.15 55.5,24.15 56.4,25.05 60.95,25.05 v1(61.325,24.675) ; CN9.5@59.13,15.2 CN10.29@64.21,15.2
  Bottom Layer w0.12: CN9.5@59.13,15.2 61.325,17.395 v1(61.325,24.675)
PB6: SB42.1 U17.58 | length 33
  Top Layer w0.12: U17.58@40.9,24.85 42.075,24.85 42.535,24.39 53.515,24.39 53.751,24.626 v1(53.978,24.626)
  Bottom Layer w0.12: SB42.1@53.6,42.85 54.565,41.885 54.565,41.6 55.525,40.64 55.525,36.614 53.975,35.064 53.978,35.062 v1(53.978,24.626)
PB7: SB44.1 U17.59 | length 33
  Top Layer w0.12: U17.59@40.9,25.35 42.104,25.35 42.579,24.875 50.425,24.875 50.625,25.075 v1(54.5,25.075)
  Bottom Layer w0.12: v1(54.5,25.075) 54.5,25.083 54.249,25.333 54.249,34.799 55.825,36.375 55.825,40.767 55,41.592 55,42.35 SB44.1@55.5,42.85
PB8: CN10.36 U17.61 | length 49.1
  Top Layer w0.12: U17.61@40.9,26.35 v1(55.3,26.35) ; v1(51.1,10.3) 56.35,10.3 57.775,8.875 65.455,8.875 CN10.36@66.75,7.58
  Bottom Layer w0.12: v1(51.1,10.3) 51.1,19.401 54.394,22.695 54.394,23.305 55.474,24.384 55.474,26.176 v1(55.3,26.35)
PB10: CN9.7 CN10.25 U17.27 | length 40.9
  Top Layer w0.12: U17.27@29.1,22.85 29.19,22.76 29.99,22.76 33.16,19.59 38.635,19.59 39.08,19.145 39.08,16.87 39.8,16.15 51.95,16.15 56.08,20.28 CN9.7@59.13,20.28 CN10.25@64.21,20.28
PB13: CN10.30 SB43.1 U17.34 | length 99.9
  Top Layer w0.12: U17.34@31.75,18.2 31.75,14.474 34.339,11.885 49.079,11.885 49.464,11.5 v1(53.175,11.5) ; v1(55.05,16.475) 65.475,16.475 CN10.30@66.75,15.2
  Bottom Layer w0.12: v1(53.175,11.5) 53.175,14.6 v1(55.05,16.475) ; SB43.1@53.6,47.5 54.6,48.5 56,48.5 57,49.5 57,50.38 57.92,51.3 61.5,51.3 62.8,52.6 68,52.6 68.7,51.9 68.7,17.15 CN10.30@66.75,15.2
PB14: CN10.28 SB45.1 U17.35 | length 96.1
  Top Layer w0.12: U17.35@32.25,18.2 v1(32.25,15.25) 32.25,14.314 34.439,12.125 53.158,12.125 53.358,11.925 v1(54,11.925) ; v1(56.325,19.025) 56.325,19.02 56.335,19.01 65.48,19.01 CN10.28@66.75,17.74
  Bottom Layer w0.12: v1(54,11.925) 54,12.525 56.525,15.05 56.525,18.79 56.325,18.99 v1(56.325,19.025) ; SB45.1@55.5,47.5 57.281,49.281 57.281,50.181 58.1,51 61.7,51 63,52.3 67.75,52.3 68.4,51.65 68.4,19.39 CN10.28@66.75,17.74
PB15: CN10.26 U17.36 | length 48
  Top Layer w0.12: U17.36@32.75,18.2 v1(32.75,14.675) 32.75,14.153 34.538,12.365 54.168,12.365 54.37,12.163 54.662,12.163 v1(54.7,12.125) ; v1(56.575,21.55) 56.575,21.539 56.664,21.45 56.764,21.55 65.48,21.55 CN10.26@66.75,20.28
  Bottom Layer w0.12: v1(54.7,12.125) 54.705,12.125 55.435,12.855 55.435,13.424 56.765,14.754 56.765,21.36 v1(56.575,21.55)
PC0: CN7.38 CN8.6 U17.8 | length 50.7
  Top Layer w0.12: CN7.38@5.79,5.04 CN8.6@10.87,5.04 ; v1(15.5,7.175) 15.5,8.217 16.211,8.928 16.211,9.032 19.73,12.551 19.73,16.226 22.024,18.52 25.591,18.52 27.936,16.175 v1(29.25,16.175) ; v1(35.15,28.45) 35.25,28.55 U17.8@35.25,30
  Bottom Layer w0.12: CN8.6@10.87,5.04 13.365,5.04 v1(15.5,7.175) ; v1(29.25,16.175) 29.25,20.15 30.025,20.925 32.75,20.925 34.04,22.215 34.04,27.34 v1(35.15,28.45)
PC1: CN7.36 CN8.5 U17.9 | length 48.4
  Top Layer w0.12: CN7.36@5.79,7.58 CN8.5@10.87,7.58 ; v1(15.5,8.825) 15.8,9.125 15.964,9.125 19.49,12.651 19.49,16.326 21.924,18.76 25.69,18.76 27.725,16.725 v1(28.6,16.725) ; v1(34.25,28.425) 34.75,28.925 U17.9@34.75,30
  Bottom Layer w0.12: CN8.5@10.87,7.58 14.255,7.58 v1(15.5,8.825) ; v1(28.6,16.725) 28.6,20.775 29.05,21.225 32.711,21.225 33.8,22.314 33.8,27.975 v1(34.25,28.425)
PC2: CN7.35 SB31.2 U17.10 | length 53
  Top Layer w0.12: CN7.35@3.25,7.58 4.47,8.8 13.5,8.8 14.1,9.4 15.9,9.4 19.25,12.75 19.25,16.425 21.825,19 26.075,19 v1@27.9,17.175 ; v1(32.95,28.45) 33.65,28.45 34.24,29.04 34.24,29.99 U17.10@34.25,30
  Bottom Layer w0.12: SB31.2@26.225,16.675 26.225,17.13 26.295,17.2 v1(27.9,17.2) 27.9,20.5 28.865,21.465 32.611,21.465 33.525,22.379 33.525,26.125 32.95,26.7 v1(32.95,28.45)
PC3: CN7.37 U17.11 | length 54.9
  Top Layer w0.12: CN7.37@3.25,5.04 4.435,6.225 12.45,6.225 14.35,8.125 v1(14.35,8.825) ; v1(14.35,29.35) 27.049,29.35 28.196,28.203 32.177,28.203 32.52,28.545 32.52,28.67 32.73,28.88 33.605,28.88 33.75,29.025 U17.11@33.75,30
  Bottom Layer w0.12: v1(14.35,8.825) v1(14.35,29.35)
PC6: CN5.2 CN10.19 U17.37 | length 53.3
  Top Layer w0.12: U17.37@33.25,18.2 33.25,13.992 34.637,12.605 54.828,12.605 55.068,12.365 55.11,12.365 v1(55.675,11.8) ; v1(57.397,29.431) 57.403,29.424 CN5.2@59.13,29.424 60.627,29.424 62.151,27.9 CN10.19@64.21,27.9
  Bottom Layer w0.12: v1(55.675,11.8) 55.675,13.325 57.005,14.655 57.005,29.03 v1@57.4,29.425
PC7: CN5.1 CN10.21 U17.38 | length 49.8
  Top Layer w0.12: U17.38@33.75,18.2 33.75,13.832 34.737,12.845 55.705,12.845 v1(56.2,12.35) ; v1(57.5,26.875) 59.121,26.875 CN5.1@59.13,26.884 60.654,25.36 CN10.21@64.21,25.36
  Bottom Layer w0.12: v1(56.2,12.35) 56.2,13.45 57.245,14.495 57.245,21.634 57.5,21.889 v1(57.5,26.875)
PC8: CN9.3 CN10.33 U17.39 | length 36.1
  Top Layer w0.12: U17.39@34.25,18.2 34.25,15.564 34.095,15.409 34.095,13.826 34.836,13.085 56.073,13.085 56.553,12.605 56.645,12.605 CN9.3@59.13,10.12 CN10.33@64.21,10.12
PC9: CN5.3 CN10.17 U17.40 | length 53.1
  Top Layer w0.12: U17.40@34.75,18.2 34.75,15.725 34.335,15.31 34.335,13.926 34.936,13.325 56.173,13.325 56.448,13.05 v1(57.15,13.05) ; CN5.3@59.13,31.964 60.654,30.44 CN10.17@64.21,30.44
  Bottom Layer w0.12: v1(57.15,13.05) 57.15,13.825 57.485,14.16 57.485,21.535 57.95,22 57.95,22.324 57.945,22.329 57.945,30.779 CN5.3@59.13,31.964
PC10: CN7.1 U17.51 | length 63.3
  Top Layer w0.12: CN7.1@3.25,50.76 4.94,52.45 17.1,52.45 v1(17.6,51.95) ; v1(32.175,23) 38.025,23 39.35,21.675 39.675,21.35 U17.51@40.9,21.35
  Bottom Layer w0.12: v1(17.6,51.95) 17.596,51.946 17.596,50.025 18.731,48.89 20.624,48.89 21.015,48.499 21.015,47.563 20.08,46.628 20.08,41.104 21.024,40.16 21.817,40.16 22.355,39.622 22.355,37.883 24.938,35.3 24.938,32.487 25.51,31.915 25.51,27.39 29.9,23 v1(32.175,23)
PC11: CN7.2 U17.52 | length 60.5
  Top Layer w0.12: CN7.2@5.79,50.76 7.1,52.07 16.48,52.07 v1(17.15,51.4) ; v1(22.125,37.35) v1(23.65,37.35) ; v1(32.975,23.45) 38.325,23.45 39.925,21.85 U17.52@40.9,21.85
  Bottom Layer w0.12: v1(17.15,51.4) 17.15,50.1 18.6,48.65 20.525,48.65 20.775,48.4 20.775,47.663 19.84,46.728 19.84,41.005 20.925,39.92 21.717,39.92 22.115,39.522 22.115,37.285 22.125,37.295 v1(22.125,37.35) ; v1(23.65,37.35) 25.178,35.822 25.178,32.587 25.75,32.014 25.75,27.6 29.9,23.45 v1(32.975,23.45)
PC12: CN7.3 U17.53 | length 63.2
  Top Layer w0.12: CN7.3@3.25,48.22 4.555,49.525 6.35,49.525 8.965,46.91 13.485,46.91 15.225,48.65 19.777,48.65 v1(20.285,48.142) ; v1(21.45,37) 21.53,36.92 23.97,36.92 v1(24.4,37.35) ; v1(32.175,23.9) 38.375,23.9 39.925,22.35 U17.53@40.9,22.35
  Bottom Layer w0.12: v1(20.285,48.142) 20.275,48.15 20.275,47.502 19.6,46.827 19.6,40.85 20.77,39.68 21.618,39.68 21.875,39.423 21.875,38.143 21.45,37.718 v1(21.45,37) ; v1(24.4,37.35) 24.4,37.3 25.418,36.282 25.418,32.686 26.08,32.024 26.08,27.695 29.75,24.025 29.875,23.9 v1(32.175,23.9)
PC13: CN7.23 SB24.2 U17.2 | length 72.7
  Top Layer w0.12: CN7.23@3.25,22.82 4.53,24.1 v1(18.325,24.1) ; v1(18.325,36.225) 18.53,36.02 25.17,36.02 26,36.85 26,38.15 v1(27.1,39.25) 27.89,40.04 v1@35.915,40.04 ; v1(38.25,28.7) U17.2@38.25,30
  Bottom Layer w0.12: v1(18.325,24.1) v1(18.325,36.225) ; v1(27.1,39.25) 26.138,38.288 26.138,32.985 26.511,32.611 26.8,32.322 26.8,30.414 27.389,29.825 SB24.2@28.175,29.825 ; v1(35.925,40.05) 35.925,35.075 38.45,32.55 38.45,29.15 38.309,29.009 38.309,28.759 v1(38.25,28.7)
PC14: CN7.25 SB22.1 | length 75
  Top Layer w0.12: CN7.25@3.25,20.28 4.495,21.525 v1(17.65,21.525) ; v1(17.275,37.35) 17.95,36.675 19.35,36.675 19.75,36.275 24.8,36.275 25.625,37.1 25.625,38.7 29.37,42.445 43.55,42.445 44.25,41.745 v1(44.25,40.375)
  Bottom Layer w0.12: v1(17.275,37.35) 17.65,36.975 v1(17.65,21.525) ; SB22.1@39.15,30.925 39.172,30.947 39.172,31.097 39.825,31.75 39.825,32.425 41.27,33.87 ; 41.27,33.878 44.25,36.858 v1(44.25,40.375)
PC15: CN7.27 SB18.1 | length 60.4
  Top Layer w0.12: CN7.27@3.25,17.74 4.51,19 v1(17.025,19) ; v1(17.025,36.15) 17.725,36.15 18.095,35.78 25.505,35.78 26.375,36.65 26.375,37.825 28.05,39.5 v1(33.175,39.5)
  Bottom Layer w0.12: v1(17.025,19) v1(17.025,36.15) ; v1(33.175,39.5) 33.175,36.875 37.74,32.31 SB18.1@37.74,30.925
PD2: CN7.4 U17.54 | length 62
  Top Layer w0.12: CN7.4@5.79,48.22 7.435,46.575 13.85,46.575 13.975,46.45 14.708,46.45 16.641,48.382 19.437,48.382 20.119,47.7 23.1,47.7 23.275,47.875 27.45,47.875 v1(28.35,46.975) ; v1(31.425,24.35) 38.425,24.35 39.925,22.85 U17.54@40.9,22.85
  Bottom Layer w0.12: v1(28.35,46.975) 27.775,46.4 27.775,43.95 27.38,43.555 27.38,41.105 25.658,39.383 25.658,32.786 26.32,32.123 26.32,27.905 29.875,24.35 v1(31.425,24.35)
PH0: CN7.29 SB19.1 | length 61
  Top Layer w0.12: CN7.29@3.25,15.2 4.525,16.475 v1(16.225,16.475) ; v1(16.225,35.775) 16.46,35.54 25.676,35.54 26.743,36.607 26.743,37.568 28.225,39.05 v1(32.6,39.05)
  Bottom Layer w0.12: v1(16.225,16.475) v1(16.225,35.775) ; v1(32.6,39.05) 32.6,36.7 36.39,32.91 SB19.1@36.39,30.925
PH1: CN7.31 SB21.1 | length 56.1
  Top Layer w0.12: CN7.31@3.25,12.66 4.515,13.925 v1(15.375,13.925) ; v1(15.375,35.3) 25.775,35.3 27.675,37.2 v1(30.025,37.2)
  Bottom Layer w0.12: v1(15.375,35.3) 15.375,13.93 v1@15.38,13.925 ; v1(30.025,37.2) 31.055,36.17 31.055,31.28 30.875,31.1
PH3_BOOT0: CN7.7 R54.2 U17.60 | length 66.3
  Top Layer w0.12: CN7.7@3.25,43.14 4.485,44.375 7.15,44.375 9.025,46.25 13.425,46.25 13.575,46.1 14.883,46.1 16.833,48.05 19.325,48.05 19.95,47.425 23.3,47.425 23.5,47.625 27,47.625 v1(28.35,46.275) ; v1(32.175,24.8) 38.05,24.8 38.137,24.887 39.1,25.85 U17.60@40.9,25.85 40.91,25.84 42.335,25.84 42.525,25.65 R54.2@43.425,25.65
  Bottom Layer w0.12: v1(28.35,46.275) 28.35,44.183 27.62,43.453 27.62,40.945 25.898,39.223 25.898,32.885 26.56,32.223 26.56,30.315 27.25,29.625 27.25,27.475 29.85,24.875 29.925,24.8 v1(32.175,24.8)
SCL: CN5.10 CN10.3 SB42.2 SB43.2 | length 15.6
  Top Layer w0.12: v1(53.6,45.1) 54.486,45.1 CN5.10@59.13,49.744 60.654,48.22 CN10.3@64.21,48.22
  Bottom Layer w0.12: SB42.2@53.6,43.95 v1(53.6,45.1) SB43.2@53.6,46.4
SDA: CN5.9 CN10.5 SB44.2 SB45.2 | length 12.7
  Top Layer w0.12: v1(55.5,45.1) 57.604,47.204 CN5.9@59.13,47.204 62.686,47.204 CN10.5@64.21,45.68
  Bottom Layer w0.12: SB44.2@55.5,43.95 v1(55.5,45.1) SB45.2@55.5,46.4
STLK_LED: R12.1 R13.2 U6.D15 | length 77.1
  Top Layer w0.12: v1@26.075,73.825 26.617,73.825 27.105,73.337 27.105,72.955 U6.D15@27.1,72.95 ; v1(26.1,57.1) 26.115,57.1 26.455,56.76 33.971,56.76 34.851,57.64 53.775,57.64 54.865,56.55 60.075,56.55 61.5,57.975 v1(61.5,61.25)
  Top Layer w0.3: R12.1@60.988,74.55 61.725,74.55 ; v1(61.725,73.975) 61.725,74.55 ; R13.2@62.47,74.55 61.725,74.55
  Bottom Layer w0.12: v1(26.075,73.85) 24.5,73.85 23.35,72.7 23.35,70.325 23.865,69.81 23.865,68.01 24.825,67.05 24.825,61.95 25.25,61.525 25.25,57.95 v1(26.1,57.1) ; v1@61.5,61.375 61.5,62.6 61.85,62.95 61.85,68.975 61.175,69.65 61.175,72.05 61.725,72.6 v1(61.725,73.975)
STLK_NRST: C1.2 JP2.1 U6.J1 | length 44.9
  Top Layer w0.12: v1(23,80.04) JP2.1@25.595,80.04 ; v1(24.8,57.65) 26.275,57.65 26.925,57 33.45,57 33.7,57.25 v1(33.7,57.3) ; U6.J1@30.35,63.85 30.852,63.348 30.852,63.015 31.384,62.483 v1(31.475,62.483)
  Bottom Layer w0.12: v1(23,80.04) 23.525,79.515 23.525,74.7 22.475,73.65 22.475,70.375 22.7,70.15 22.7,61.95 24.8,59.85 v1(24.8,57.65) ; v1(31.475,62.483) 31.483,62.475 33.217,62.475 33.7,61.992 v1(33.7,57.3)
STLK_OSC_IN: C41.1 U6.G1 X1.1 | length 7.2
  Top Layer w0.12: C41.1@27.875,58.375 27.9,58.4 X1.1@29,58.4 29.05,58.4 29.675,59.025 29.675,60.1 29.05,60.725 U6.G1@29.05,63.85
STLK_OSC_OUT: C40.1 U6.H1 X1.3 | length 6
  Top Layer w0.12: U6.H1@29.7,63.85 29.5,63.65 29.5,60.8 30.35,59.95 X1.3@30.35,59.45 C40.1@31.5,59.45
STLK_SWCLK: CN2.2 U6.A14 | length 16
  Top Layer w0.12: CN2.2@15.255,80.04 16.495,78.8 22.125,78.8 23.3,77.625 ; 23.018,77.918 23.565,77.37 23.565,76.584 23.3,76.319 23.3,73.75 23.75,73.3 24.15,73.3 U6.A14@25.15,72.3
STLK_SWDIO: CN2.4 U6.A15 | length 10.2
  Top Layer w0.12: CN2.4@20.335,80.04 20.47,79.905 21.37,79.905 23.805,77.47 23.805,76.485 23.54,76.22 23.54,73.985 23.925,73.6 24.5,73.6 U6.A15@25.15,72.95
STLK_UCPD_CC1_C: C18.1 R34.2 U6.M5 | length 25.1
  Top Layer w0.12: U6.M5@32.3,66.45 32.625,66.125 34.55,66.125 34.595,66.08 34.92,66.08 35.115,65.885 35.385,65.885 35.565,65.705 37.001,65.705 37.266,65.97 v1(37.275,65.97) ; R34.2@49.95,70.225 50.725,70.225 C18.1@50.75,70.2 v1(50.75,70.875)
  Bottom Layer w0.12: v1(37.275,65.97) 37.275,66.65 37.775,67.15 37.775,69.567 37.956,69.748 41.524,69.748 42.697,68.575 48.45,68.575 50.675,70.8 v1@50.7,70.8
STLK_UCPD_CC2_C: C7.1 R5.2 U6.N5 | length 15.4
  Top Layer w0.12: U6.N5@32.95,66.45 33.15,66.45 33.475,66.775 34.925,66.775 35.151,66.549 v1(35.554,66.549) ; C7.1@37.925,75.875 38.05,76 R5.2@38.797,76 R5.2@38.8,76 ; C7.1@37.997,75.95 38,75.953 v1(38,76.575)
  Bottom Layer w0.12: v1(35.554,66.549) 35.554,67.004 35.75,67.2 35.75,74.325 36.925,75.5 v1(38,76.575)
STLK_USB_CN_N: CN1.A7 CN1.B7 U8.5 | length 8.6
  Top Layer w0.155: U8.5@45.659,70.256 v1(46.484,70.256) ; v1(46.482,71.323) 47.142,71.323 47.401,71.582 47.401,73.043 CN1.A7@47.342,73.103 ; v1(48.092,73.982) CN1.B7@48.092,74.803
  Bottom Layer w0.155: v1(46.484,70.256) 46.484,71.321 v1(46.482,71.323) 48.092,72.933 v1(48.092,73.982)
STLK_USB_CN_P: CN1.A6 CN1.B6 U8.6 | length 5.9
  Top Layer w0.155: U8.6@45.659,70.756 47.114,70.756 47.782,71.424 47.782,73.044 CN1.A6@47.842,73.103 47.842,73.596 47.592,73.846 CN1.B6@47.592,74.803
STLK_USB_N: U6.R14 U8.2 | length 11.1
  Top Layer w0.155: U6.R14@34.25,72.3 34.254,72.3 34.388,72.435 35.49,72.435 36.052,72.434 36.977,71.509 41.834,71.509 43.027,70.316 44.045,70.316 44.057,70.304 44.311,70.304 U8.2@44.359,70.256
STLK_USB_P: U6.R15 U8.1 | length 11.1
  Top Layer w0.155: U6.R15@34.25,72.95 34.254,72.95 34.388,72.816 35.648,72.816 36.21,72.815 37.135,71.89 41.992,71.89 43.185,70.697 44.045,70.697 44.057,70.709 44.311,70.709 U8.1@44.359,70.756
STLK_VCP_RX: R18.1 R104.1 U3.5 U6.C10 | length 16.9
  Top Layer w0.12: R18.1@16.053,74.5 v1(16.575,74.5) 17.075,74.5 17.2,74.625 U3.5@17.45,74.625 ; v1(17.7,70.6) 22.455,70.6 22.595,70.46 23.955,70.46 24.675,69.74 24.675,69.55 24.85,69.375 26.125,69.375 U6.C10@26.45,69.7
  Bottom Layer w0.12: v1(16.575,74.5) 17.075,74 R104.1@18.25,74 ; v1(17.7,70.6) 18.69,71.59 18.69,73.475 18.455,73.71 18.445,73.71 18.25,73.905 R104.1@18.25,74 ; R104.1@18.3,74 R104.1@18.25,74
STLK_VCP_TX: R4.1 R106.1 U2.3 U6.A7 | length 28.6
  Top Layer w0.12: R4.1@6.9,76.225 v1(7.525,76.225) 8.125,75.625 U2.3@8.675,75.625 ; v1(8.325,71.525) 9.225,71.525 10.4,70.35 15.426,70.35 18.026,67.75 U6.A7@25.15,67.75
  Bottom Layer w0.12: v1(8.325,71.525) 7.386,71.525 6.735,72.176 6.735,75.435 v1(7.525,76.225) 8.205,76.225 8.73,76.75 R106.1@9.3,76.75
SW_DIR: R26.2 U2.10 U6.R3 | length 51.6
  Top Layer w0.12: v1(10.95,80.7) 11.56,81.31 34.015,81.31 35.052,80.273 v1(35.052,75.819) ; U2.10@11.075,73.625 11.165,73.535 11.44,73.535 v1(11.8,73.175) 11.835,73.175 12.06,72.95 R26.2@12.625,72.95 ; U6.R3@34.25,65.15 34.707,65.15 34.962,64.895 v1(34.975,64.895)
  Bottom Layer w0.12: v1(10.95,80.7) 10.95,79.37 12.36,77.96 12.36,73.735 v1(11.8,73.175) ; v1(34.975,64.895) 34.975,66.764 35.51,67.299 35.51,75.361 v1(35.052,75.819)
SWCLK_BP: R2.1 R107.2 U2.13 | length 4.7
  Top Layer w0.12: U2.13@11.075,75.125 11.65,75.125 12.075,75.55 12.075,76.525 12.26,76.71 12.43,76.71 12.625,76.905 R2.1@12.625,76.925
  Bottom Layer w0.12: R107.2@10.2,75.75 11.575,75.75 11.82,75.505 v1@11.82,75.36
  other v1: 11.93,75.395
SWDIO_BP: R6.1 R17.1 R108.2 U2.12 | length 4.8
  Top Layer w0.12: U2.12@11.075,74.625 11.08,74.63 11.825,74.63 v1(11.83,74.635) 12.095,74.9 R17.1@12.625,74.9 R6.1@12.625,75.9 ; R17.1@12.43,74.625 R17.1@12.625,74.82
  Bottom Layer w0.12: R108.2@10.2,74 11.195,74 11.75,74.555 v1@11.75,74.62
T_JRCLK: R22.1 R105.1 U3.6 U6.A10 | length 16.5
  Top Layer w0.12: R22.1@16.075,73.5 v1@16.565,73.5 ; v1(16.575,70.6) 17.01,71.035 18.04,71.035 18.235,70.84 22.554,70.84 22.66,70.734 22.694,70.7 24.054,70.7 24.339,70.414 24.704,70.05 24.8,70.05 U6.A10@25.15,69.7 ; v1(16.575,73.5) v1@16.565,73.5 ; U3.6@17.45,74.125 16.825,74.125 16.565,73.865 v1@16.565,73.5
  Bottom Layer w0.12: v1(16.575,70.6) 16.575,70.62 17.33,71.375 17.81,71.375 18.25,71.815 R105.1@18.25,73 ; v1(16.575,73.5) 17.8,73.5 18.01,73.29 18.055,73.29 R105.1@18.3,73.045
T_JTDI: R24.2 R109.1 U2.6 U6.L3 | length 34
  Top Layer w0.12: R24.2@6.975,73 v1(7.725,73) ; v1@7.75,73 7.725,73.025 7.725,73.7 7.97,73.945 7.973,73.945 8.153,74.125 8.225,74.125 U2.6@8.675,74.125 ; v1(8.95,71.075) 9.314,71.075 10.289,70.1 15.336,70.1 17.961,67.475 18.7,67.475 22.3,63.875 23.775,63.875 24.78,64.88 24.78,65.33 24.925,65.475 25.976,65.475 26.139,65.638 26.139,65.945 26.319,66.125 27.525,66.125 27.575,66.175 31.15,66.175 31.325,66 31.325,65.475 U6.L3@31.65,65.15
  Bottom Layer w0.12: v1(7.725,73) 8.475,72.25 R109.1@9.55,72.25 9.55,72.155 8.95,71.555 v1(8.95,71.075)
T_MCO: R3.2 R8.2 R102.1 TP1.1 U3.3 | length 21.5
  Top Layer w0.12: R3.2@15.95,76.5 R3.2@15.975,76.5 ; v1(15.975,78.1) R3.2@15.975,76.5 ; U3.3@17.45,75.625 16.898,75.625 16.743,75.78 v1(16.64,75.78) 16.595,75.825 16.595,76.355 16.45,76.5 R3.2@15.975,76.5 ; R8.2@26.5,75.875 v1(26.5,76.725) TP1.1@26.5,77.6
  Bottom Layer w0.12: v1(15.975,78.1) 16.536,78.661 20.661,78.661 22.675,80.675 24.15,80.675 24.525,80.3 24.525,78.7 v1(26.5,76.725) ; v1(16.64,75.78) 17.61,76.75 R102.1@18.05,76.75
T_PWR_EN: R35.2 R37.2 U1.4 U5.2 U6.R5 | length 39.5
  Top Layer w0.12: U6.R5@34.25,66.45 34.9,66.45 35.225,66.125 35.484,66.125 35.584,66.025 36.65,66.025 37.745,67.12 37.745,67.37 38.375,68 40.825,68 41.275,68.45 v1(51.9,68.45) ; R37.2@51.2,66.75 52.2,66.75 52.275,66.675 53.025,66.675 v1@53.05,66.7 ; v1(53.075,66.675) 53.075,66.714 53.25,66.889 U5.2@53.25,67.35 ; v1(61.3,68.875) 63.425,68.875 63.675,69.125 R35.2@63.675,69.65
  Top Layer w0.2: R35.2@63.7,69.75 64.3,69.75 64.4,69.65 U1.4@65,69.65
  Bottom Layer w0.12: v1@51.9,68.375 51.9,67.85 v1(53.075,66.675) ; v1(51.9,68.45) 52.273,68.823 53.91,68.823 54.356,68.377 55.067,68.377 57.29,70.6 59.575,70.6 v1(61.3,68.875)
T_PWR_EXT: R38.1 R39.1 U6.R4 | length 5.5
  Top Layer w0.2: U6.R4@34.25,65.8 34.8,65.8 34.995,65.605 35.269,65.605 35.449,65.425 37.775,65.425 37.995,65.645 38.195,65.645 R38.1@38.35,65.8 R39.1@39.4,65.8
T_PWR_INT: C73.1 R27.2 R29.1 R31.1 U1.3 U6.J2 | length 49.9
  Top Layer w0.12: U6.J2@30.35,64.5 30.664,64.186 31.098,64.186 31.333,63.951 31.333,63.261 v1(31.42,63.174) ; v1(64.35,72.725) 63.7,72.075 R29.1@63.7,71.75 63.8,71.85 U1.3@65.05,71.85
  Bottom Layer w0.12: v1@31.42,63.12 31.783,63.483 C73.1@31.783,64.033 31.783,64.523 32.004,64.745 33.375,64.745 R31.1@33.761,64.358 35.664,64.358 R27.2@35.738,64.433 35.738,65.557 36.735,66.555 36.735,70.238 36.982,70.485 40.284,70.485 40.589,70.18 41.91,70.18 43.078,69.012 48.061,69.012 50.524,71.476 52.38,71.476 52.805,71.051 54.326,71.051 55.285,72.009 56.798,72.009 58.209,73.42 58.209,74.969 58.54,75.3 61.775,75.3 v1(64.35,72.725)
T_PWR_LED: R10.2 R11.2 U6.H15 | length 42.7
  Top Layer w0.12: U6.H15@29.7,72.95 29.686,72.964 29.686,73.127 29.65,73.163 29.65,73.375 28.3,74.725 28.3,76.975 28.775,77.45 29.725,77.45 30.137,77.038 v1(31.648,77.038) ; R11.2@57.425,74.55 57.455,74.52 v1(57.455,73.762)
  Top Layer w0.3: R10.2@55.925,74.55 R11.2@57.425,74.55
  Bottom Layer w0.12: v1(31.648,77.038) 38.456,77.038 44.069,71.425 44.069,70.688 45.263,69.494 47.919,69.494 50.332,71.907 52.476,71.907 52.982,71.401 54.113,71.401 55.053,72.341 55.053,73.304 55.51,73.762 v1(57.455,73.762)
T_PWR_SEL1: R23.2 U6.D10 | length 42.3
  Top Layer w0.12: v1(24.73,70.7) 24.735,70.695 25.93,70.695 26.145,70.48 26.145,70.105 26.225,70.025 26.775,70.025 U6.D10@27.1,69.7 ; v1@54.2,73.425 54.225,73.45 R23.2@55,73.45
  Bottom Layer w0.12: v1(24.73,70.7) 24.735,70.695 26.645,70.695 27.225,71.275 27.225,74.875 28.275,75.925 28.275,77.07 29.488,78.283 38.752,78.283 40.276,76.759 52.832,76.759 54.175,75.416 v1(54.175,73.45)
T_PWR_SEL2: R30.2 U6.C11 | length 38.8
  Top Layer w0.12: U6.C11@26.45,70.35 26.775,70.675 27.206,70.675 27.381,70.5 v1(27.775,70.5) ; R30.2@53.275,71.3 v1(53.275,72.1)
  Bottom Layer w0.12: v1(27.775,70.5) 27.775,74.9 28.565,75.69 28.565,77.015 29.593,78.043 38.652,78.043 40.19,76.505 52.386,76.505 53.275,75.616 v1(53.275,72.1)
T_SWCLK: R15.1 R107.1 U2.4 U6.M6 U6.M11 | length 46.2
  Top Layer w0.12: R15.1@6.9,75.15 6.925,75.125 7.27,75.125 v1(7.595,75.45) ; v1@7.625,75.45 7.625,75.42 7.92,75.125 U2.4@8.675,75.125 ; v1(7.725,71.975) 11.625,71.975 12.325,71.275 23.524,71.275 23.674,71.425 v1(24.3,71.425) ; v1(30.35,70.325) 30.67,70.005 31.222,70.005 31.567,70.35 U6.M11@32.3,70.35 ; U6.M6@32.3,67.1 32.519,67.1 32.844,67.425 34.5,67.425 34.625,67.55 v1(35.025,67.55)
  Bottom Layer w0.12: v1(7.725,71.975) 7.715,71.985 7.265,71.985 6.975,72.275 6.975,74.83 v1(7.595,75.45) 7.61,75.465 8.25,75.465 8.535,75.75 R107.1@9.3,75.75 ; v1@24.3,71.4 24.3,70.45 24.775,69.975 30,69.975 v1(30.35,70.325) 30.35,70.85 30.6,71.1 34.375,71.1 35.25,70.225 35.25,69.051 35.025,68.826 v1(35.025,67.55)
T_SWDIO: R19.2 R108.1 U2.5 U6.L2 U6.N12 | length 38.6
  Top Layer w0.12: R19.2@6.9,74.075 7.495,74.075 v1(7.795,74.375) ; v1@7.775,74.375 v1(7.795,74.375) ; U2.5@8.675,74.625 8.068,74.625 7.818,74.375 v1(7.795,74.375) ; v1(10.9,73.025) 10.914,73.025 12.404,71.535 23.445,71.535 v1(23.78,71.87) ; v1(31,70.475) 31.06,70.535 31.31,70.535 31.425,70.65 31.731,70.65 31.995,70.914 31.995,71.126 32.174,71.305 32.645,71.305 U6.N12@32.95,71 32.625,70.675 32.625,67.6 32.43,67.405 32.136,67.405 31.975,67.244 31.975,64.825 U6.L2@31.65,64.5
  Bottom Layer w0.12: v1(7.795,74.375) 8.285,74.375 8.66,74 R108.1@9.3,74 9.3,73.905 10.18,73.025 v1(10.9,73.025) ; v1(23.78,71.87) 23.78,70.57 24.625,69.725 30.75,69.725 31,69.975 v1(31,70.475)
T_SWO: R9.1 R103.1 U3.4 U6.A6 U6.D12 | length 25.2
  Top Layer w0.12: R9.1@16.096,75.426 16.145,75.475 16.3,75.475 v1(16.64,75.135) 16.645,75.13 17.445,75.13 U3.4@17.45,75.125 ; v1(17.7,72.075) 18.36,72.075 18.66,71.775 22.38,71.775 v1(22.905,72.3) 24.2,72.3 24.725,71.775 24.725,71.535 24.93,71.33 26.77,71.33 U6.D12@27.1,71 ; v1(24.375,66.819) 24.656,67.1 U6.A6@25.15,67.1
  Bottom Layer w0.12: v1@16.621,75.154 16.145,74.678 16.145,72.497 16.567,72.075 v1(17.7,72.075) ; v1@16.625,75.135 v1(16.64,75.135) v1@16.665,75.16 ; v1@16.69,75.135 17.525,75.135 17.655,75.265 17.66,75.265 18.05,75.655 R103.1@18.05,75.75 ; v1(22.905,72.3) 22.905,70.395 23.625,69.675 23.625,67.569 24.344,66.85 v1@24.375,66.85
